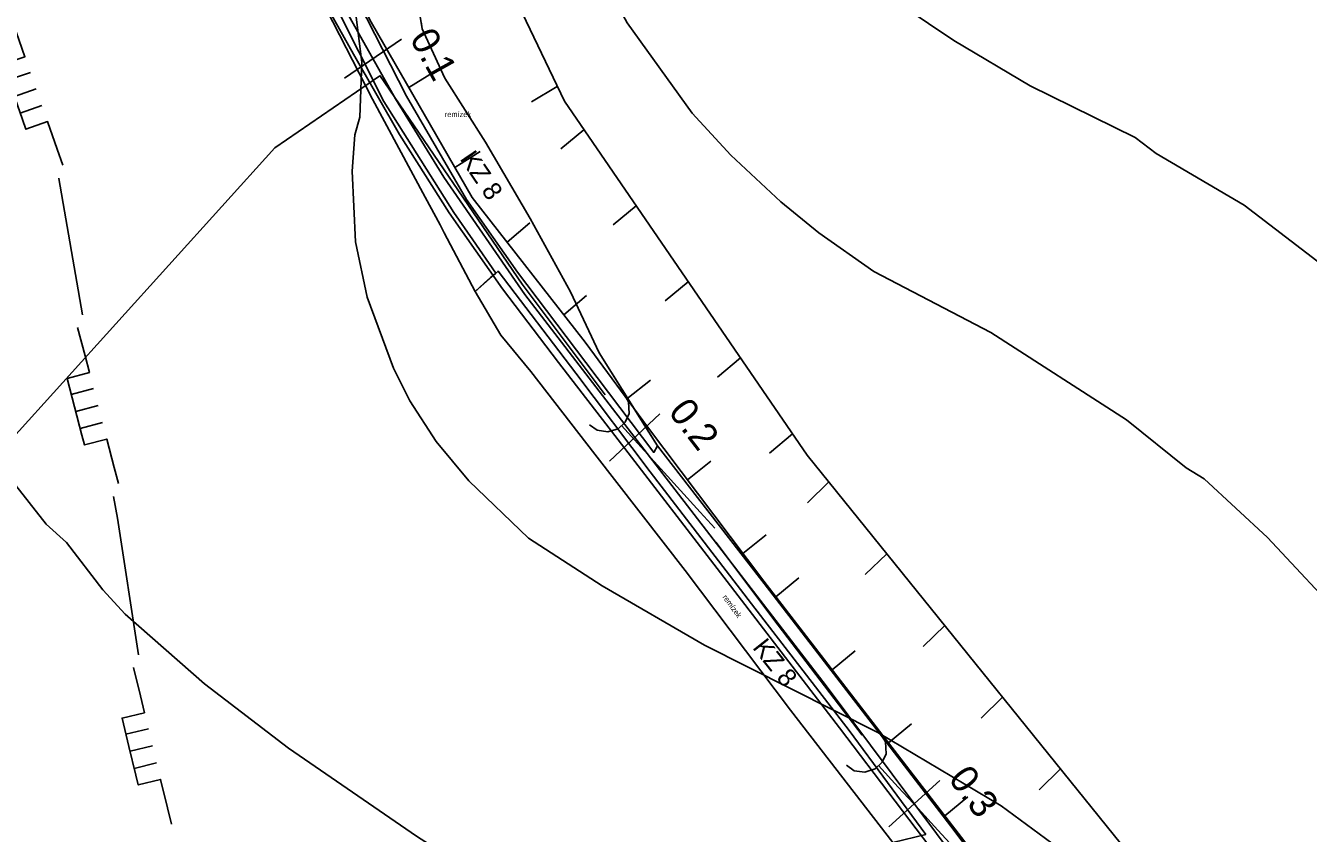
# Model space of a CAD drawing. Extents: x -645676 to -642474, y -1077513 to -1072613.
# Drawn here: x -643719.5 to -643441.2, y -1073932.9 to -1073757.7 of the extents above; entities that cross this region are included whole.
import ezdxf

# ---------------------------------------------------------------- set-up
doc = ezdxf.new("R2010")
doc.units = 0
for name, color, linetype in [('Kanalizace', 7, 'Continuous'), ('KRAJ_ZELEN_STAV', 7, 'Continuous'), ('Krajinn__zele____popis___stav', 7, 'Continuous'), ('KULTURY_STAV', 7, 'Continuous'), ('Odvodnen__cesty_pr_kopem___navr_en_', 7, 'Continuous'), ('PC_NAVRH', 7, 'Continuous'), ('PC_STAN_NAVRH', 7, 'Continuous'), ('PLYNOVOD', 7, 'Continuous'), ('USES_BK_NAVRH', 7, 'Continuous'), ('VRSTEVNICE', 7, 'Continuous')]:
    doc.layers.add(name, color=color, linetype=linetype)

# ---------------------------------------------------------------- blocks, each defined once
blk = doc.blocks.new('$944')
blk.add_line((0, 1.5), (0, -1.5))
blk = doc.blocks.new('2$1030')
blk.add_line((0, 0), (0, -0.5))
blk = doc.blocks.new('6$2320')
for points in [[(-3.48, 1), (-3.08, 0.92), (-2.68, 0.6), (-2.53, 0.22), (-2.52, -0.2), (-2.72, -0.62), (-3.08, -0.92), (-3.48, -1)], [(-2.53, 0), (-1.26, 0), (0.01, 0), (1.28, 0), (2.55, 0), (3.5, 0)]]:
    blk.add_lwpolyline(points)
blk = doc.blocks.new('6$3520')
for p, q in [((-0.76, 0), (-0.76, -1)), ((0, -1), (0, 0)), ((0.76, 0), (0.76, -1))]:
    blk.add_line(p, q)
blk.add_lwpolyline([(-3.5, 0), (-2.23, 0), (-1.48, 0), (-1.48, -1), (-0.21, -1), (1.06, -1), (1.5, -1), (1.5, 0), (2.77, 0), (3.5, 0)])

msp = doc.modelspace()

# ---------------------------------------------------------------- linework, layer by layer
at = {"layer": 'Kanalizace'}
for p, q in [((-643665.44, -1073784.24), (-643642.65, -1073768.58)), ((-643642.66, -1073768.55), (-643611.78, -1073813.81)), ((-643723.01, -1073847.87), (-643665.44, -1073784.24)), ((-643723.01, -1073847.87), (-643665.44, -1073784.24)), ((-643611.78, -1073813.81), (-643593.76, -1073837.8)), ((-643569.75, -1073869.78), (-643556.24, -1073887.78)), ((-643556.24, -1073887.78), (-643538.04, -1073911.63))]:
    msp.add_line(p, q, dxfattribs=at)
at = {"layer": 'KRAJ_ZELEN_STAV'}
for points in [[(-643649.01, -1073749.31), (-643634.94, -1073749.48), (-643633.51, -1073758.38), (-643628.59, -1073769.13), (-643619.76, -1073783.01), (-643610.08, -1073799.51), (-643601.34, -1073815.46), (-643595.06, -1073828.7), (-643582.45, -1073848.84), (-643583.26, -1073850.28), (-643597.98, -1073830.78), (-643612.79, -1073811.21), (-643623.9, -1073795.39), (-643636.91, -1073773.03), (-643649.01, -1073749.31)], [(-643524.22, -1073933.15), (-643531.39, -1073934.89), (-643553.59, -1073906.22), (-643576.42, -1073875.87), (-643596.05, -1073850.64), (-643609.95, -1073832.7), (-643616.42, -1073824.85), (-643622.03, -1073815.34), (-643617.04, -1073810.95), (-643600.15, -1073833.11), (-643583.99, -1073854.5), (-643562.02, -1073883.13), (-643540.85, -1073910.59), (-643524.22, -1073933.15)]]:
    msp.add_lwpolyline(points, dxfattribs=at)
at = {"layer": 'KULTURY_STAV'}
for points in [[(-643531.39, -1073934.89), (-643553.59, -1073906.22), (-643576.42, -1073875.87), (-643596.05, -1073850.64), (-643609.95, -1073832.7), (-643616.42, -1073824.85), (-643622.03, -1073815.34), (-643620.02, -1073813.58), (-643618.65, -1073812.37), (-643618.11, -1073811.9), (-643617.52, -1073811.38), (-643622.48, -1073804.19), (-643626.59, -1073798.22), (-643641.81, -1073774.19), (-643652.73, -1073752.46), (-643665.22, -1073728.64), (-643666.54, -1073726.12), (-643673.23, -1073715.26), (-643674.23, -1073713.83), (-643684.96, -1073698.46), (-643693.51, -1073689.09), (-643698.79, -1073685.95), (-643703.72, -1073691.87), (-643740.99, -1073734.31)], [(-643703.72, -1073691.87), (-643702.9, -1073692.32), (-643695.83, -1073691.91), (-643683.82, -1073705.29), (-643673.45, -1073721.42), (-643669.49, -1073727.58), (-643664.51, -1073736.29), (-643654.36, -1073754.02), (-643644.24, -1073773.66), (-643632.82, -1073794.91), (-643629.6, -1073800.91), (-643628.7, -1073802.62), (-643622.03, -1073815.34), (-643616.42, -1073824.85), (-643609.95, -1073832.7), (-643596.05, -1073850.64), (-643576.42, -1073875.87), (-643553.59, -1073906.22), (-643531.39, -1073934.89)], [(-643652.73, -1073752.46), (-643641.81, -1073774.19), (-643626.59, -1073798.22), (-643622.48, -1073804.19), (-643617.52, -1073811.38), (-643618.11, -1073811.9), (-643618.65, -1073812.37), (-643620.02, -1073813.58), (-643622.03, -1073815.34), (-643628.7, -1073802.62), (-643629.6, -1073800.91), (-643632.82, -1073794.91), (-643644.24, -1073773.66), (-643654.36, -1073754.02)], [(-643633.75, -1073756.87), (-643633.51, -1073758.38), (-643628.59, -1073769.13), (-643619.76, -1073783.01), (-643610.08, -1073799.51), (-643601.34, -1073815.46), (-643595.06, -1073828.7), (-643584.78, -1073845.12), (-643582.45, -1073848.84), (-643575.45, -1073857.86), (-643558.06, -1073880.28), (-643556.61, -1073882.16), (-643537.19, -1073907.35), (-643518.04, -1073932.33), (-643502.09, -1073953.62)], [(-643502.09, -1073953.62), (-643518.04, -1073932.33), (-643537.19, -1073907.35), (-643556.61, -1073882.16), (-643558.06, -1073880.28), (-643575.45, -1073857.86), (-643582.45, -1073848.84), (-643584.78, -1073845.12), (-643595.06, -1073828.7), (-643601.34, -1073815.46), (-643610.08, -1073799.51), (-643619.76, -1073783.01), (-643628.59, -1073769.13), (-643633.51, -1073758.38), (-643633.75, -1073756.87)]]:
    msp.add_lwpolyline(points, dxfattribs=at)
at = {"layer": 'Odvodnen__cesty_pr_kopem___navr_en_'}
msp.add_lwpolyline([(-643518.78, -1073941.84), (-643542.91, -1073910.01), (-643567.3, -1073878.31), (-643591.69, -1073846.61), (-643603.89, -1073830.76), (-643616.06, -1073814.8), (-643627.63, -1073798.31), (-643638.41, -1073781.29), (-643648.42, -1073763.86), (-643658.18, -1073746.41), (-643667.95, -1073728.96), (-643677.91, -1073712.02), (-643690.42, -1073696.75), (-643693.93, -1073692.17), (-643696.47, -1073689.99), (-643699.11, -1073689.1), (-643701.32, -1073689.14)], dxfattribs=at)
at = {"layer": 'PC_NAVRH'}
msp.add_lwpolyline([(-643699.19, -1073681.85), (-643673.6, -1073712.41), (-643664.43, -1073728.78), (-643639.3, -1073773.55), (-643628.83, -1073790.6), (-643611.21, -1073816.03), (-643592.93, -1073839.85), (-643545.81, -1073900.9), (-643507.54, -1073952.15), (-643483.08, -1073986.87), (-643435.34, -1074054.23), (-643374.17, -1074125.66), (-643332.32, -1074171.6), (-643301.24, -1074200.87), (-643248.32, -1074243.3), (-643194.15, -1074284.9), (-643147.82, -1074320.78)], dxfattribs=at)
at = {"layer": 'PLYNOVOD'}
for points in [[(-643712.33, -1073790.81), (-643712.32, -1073790.85), (-643707.23, -1073820.42)], [(-643700.45, -1073859.84), (-643699.64, -1073864.53), (-643695.07, -1073894.18)]]:
    msp.add_lwpolyline(points, dxfattribs=at)
at = {"layer": 'USES_BK_NAVRH'}
for points in [[(-643365.02, -1074664.02), (-643154.25, -1074308.76), (-643202.04, -1074272.42), (-643254.74, -1074231.15), (-643281.49, -1074209.44), (-643326.14, -1074172.74), (-643340.63, -1074157.75), (-643367.66, -1074127.85), (-643392.35, -1074099.24), (-643419.6, -1074067.32), (-643456.29, -1074020.07), (-643488.65, -1073967.87), (-643493.42, -1073961.92), (-643503.27, -1073950.91), (-643559.37, -1073878.23), (-643584.6, -1073844.72), (-643598.15, -1073826.35), (-643622.66, -1073794.97), (-643644.55, -1073756.98), (-643662.32, -1073721.99), (-643645.55, -1073647.06), (-643529.9, -1073432)], [(-643507.19, -1073442.54), (-643621.79, -1073655.66), (-643633.31, -1073710.01), (-643602.63, -1073774.11), (-643549.96, -1073850.87), (-643465.95, -1073954.88), (-643402.48, -1074047.21), (-643374.54, -1074085.13), (-643322.34, -1074142.15), (-643301.3, -1074161.69), (-643132.86, -1074291.27), (-643133.86, -1074292.82), (-643146.7, -1074315.23), (-643153.67, -1074324.49), (-643140.05, -1074334.77), (-643371.48, -1074723.77)]]:
    msp.add_lwpolyline(points, dxfattribs=at)
at = {"layer": 'VRSTEVNICE'}
for points in [[(-643571.57, -1073679.89), (-643568.68, -1073690.49), (-643567.95, -1073693.86), (-643563.81, -1073707.22), (-643556.55, -1073723.45), (-643545.01, -1073739.4), (-643534.62, -1073749.8), (-643518.1, -1073760.91), (-643501.58, -1073770.74), (-643478.79, -1073781.99), (-643474.23, -1073785.41), (-643455.15, -1073796.66), (-643435.92, -1073811.33), (-643432.07, -1073815.74), (-643418.97, -1073828.27), (-643389.21, -1073860.46), (-643365.28, -1073881.97)], [(-643369.98, -1073943.49), (-643387.64, -1073931.1), (-643401.88, -1073919.57), (-643411.14, -1073910.74), (-643429.94, -1073890.23), (-643431.93, -1073887.38), (-643432.5, -1073887.52), (-643450.02, -1073868.72), (-643463.83, -1073856.05), (-643467.68, -1073853.63), (-643480.64, -1073843.23), (-643510.12, -1073824.29), (-643535.47, -1073811.04), (-643547.44, -1073802.64), (-643555.7, -1073795.95), (-643566.52, -1073785.83), (-643574.92, -1073776.72), (-643589.02, -1073757.06), (-643596, -1073744.25), (-643605.25, -1073712.36)], [(-643495.45, -1073936.09), (-643507.84, -1073926.97), (-643534.62, -1073911.02), (-643572.22, -1073892.08), (-643594.43, -1073879.26), (-643610.39, -1073868.86), (-643623.35, -1073856.47), (-643630.47, -1073847.93), (-643636.16, -1073839.1), (-643639.72, -1073831.98), (-643645.42, -1073816.6), (-643647.98, -1073804.63), (-643648.7, -1073789.25), (-643648.13, -1073781.42), (-643646.99, -1073777.57), (-643646.56, -1073765.61), (-643648.84, -1073747.66)], [(-643259.03, -1074363.78), (-643284.67, -1074336.72), (-643289.51, -1074332.73), (-643308.17, -1074319.91), (-643324.12, -1074306.52), (-643343.77, -1074285.59), (-643376.1, -1074243.58), (-643398.89, -1074211.1), (-643433.07, -1074155.84), (-643478.08, -1074088.34), (-643513.4, -1074039.91), (-643533.34, -1074014.85), (-643551.14, -1073996.19), (-643567.8, -1073980.95), (-643581.33, -1073969.84), (-643605.12, -1073952.47), (-643634.74, -1073933.52), (-643662.51, -1073914.44), (-643680.74, -1073900.48), (-643697.97, -1073885.39), (-643702.82, -1073880.12), (-643710.65, -1073869.86), (-643715.06, -1073865.87), (-643722.47, -1073856.47)]]:
    msp.add_lwpolyline(points, dxfattribs=at)

# ---------------------------------------------------------------- block references
at = {"layer": 'Kanalizace', "xscale": 5}
for p, yscale, rotation in [((-643581.76, -1073853.79), 4.999999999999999, -47.74337400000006), ((-643525.91, -1073927.53), 5, -47.292080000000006)]:
    msp.add_blockref('6$2320', p, dxfattribs=dict(at, yscale=yscale, rotation=rotation))
at = {"layer": 'PC_STAN_NAVRH', "xscale": 5, "yscale": 5}
for p, rotation in [((-643644.18, -1073764.86), -55.46284900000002), ((-643587.39, -1073847.03), -46.969155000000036), ((-643526.69, -1073926.5), -47.890229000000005)]:
    msp.add_blockref('$944', p, dxfattribs=dict(at, rotation=rotation))
at = {"layer": 'PLYNOVOD', "yscale": 5}
for p, xscale, rotation in [((-643717.27, -1073771.43), 5, -70.74596600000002), ((-643703.84, -1073840.13), 4.999999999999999, -75.35250000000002), ((-643692.02, -1073913.95), 4.999999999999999, -76.366)]:
    msp.add_blockref('6$3520', p, dxfattribs=dict(at, xscale=xscale, rotation=rotation))
at = {"layer": 'USES_BK_NAVRH'}
for p, xscale, yscale, rotation in [((-643636.39, -1073771.15), 13, 13.000000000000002, 122.042083), ((-643604.17, -1073770.89), 13, 13, -59.260195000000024), ((-643598.38, -1073780.29), 13, 13, -50.23212000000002), ((-643626.41, -1073788.48), 13, 13.000000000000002, 122.042083), ((-643587.07, -1073796.78), 13, 13, -50.23212000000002), ((-643615.08, -1073804.68), 13.000000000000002, 12.999999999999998, 130.224555), ((-643575.75, -1073813.27), 13, 13, -50.23212000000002), ((-643602.77, -1073820.44), 13.000000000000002, 12.999999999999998, 130.224555), ((-643564.44, -1073829.77), 13, 13, -50.23212000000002), ((-643589.05, -1073838.68), 13.000000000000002, 12.999999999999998, 128.643484), ((-643553.12, -1073846.26), 13, 13, -50.23212000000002), ((-643575.9, -1073856.26), 13, 13, 129.188984), ((-643545.25, -1073856.7), 13, 13, -45.679707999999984), ((-643563.88, -1073872.24), 13, 13, 129.188984), ((-643532.68, -1073872.26), 13, 13, -45.679707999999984), ((-643556.73, -1073881.65), 12.999999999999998, 13.000000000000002, 129.890984), ((-643520.11, -1073887.82), 13, 13, -45.679707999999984), ((-643544.51, -1073897.48), 12.999999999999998, 13.000000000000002, 129.890984), ((-643507.55, -1073903.38), 13, 13, -45.679707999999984), ((-643532.29, -1073913.31), 12.999999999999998, 13.000000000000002, 129.890984), ((-643494.98, -1073918.94), 13, 13, -45.679707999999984), ((-643520.07, -1073929.14), 12.999999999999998, 13.000000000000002, 129.890984)]:
    msp.add_blockref('2$1030', p, dxfattribs=dict(at, xscale=xscale, yscale=yscale, rotation=rotation))

# ---------------------------------------------------------------- texts
at = {"layer": 'Krajinn__zele____popis___stav'}
msp.add_text('remízek', height=1.2, dxfattribs=at).set_placement((-643628.59, -1073777.54))
for s, height, rotation, p in [('KZ 8', 4, 304.194, (-643625.44, -1073786.59)), ('remízek', 1.2, 306.027, (-643568.39, -1073881.7)), ('KZ 8', 4, 308.319, (-643561.95, -1073892.67))]:
    msp.add_text(s, height=height, rotation=rotation, dxfattribs=at).set_placement(p)
at = {"layer": 'PC_STAN_NAVRH'}
for s, rotation, p in [('0.1', 299.313, (-643636.33, -1073760.45)), ('0.2', 307.678, (-643580.27, -1073841.52)), ('0.3', 306.762, (-643519.49, -1073921.11))]:
    msp.add_text(s, height=6, rotation=rotation, dxfattribs=at).set_placement(p)

doc.saveas('drawing.dxf')
